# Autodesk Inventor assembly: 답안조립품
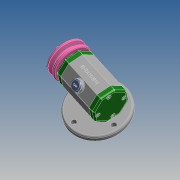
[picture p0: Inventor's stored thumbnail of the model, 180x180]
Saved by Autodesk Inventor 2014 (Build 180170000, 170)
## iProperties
Created: 2021-02
Part Number: 답안조립품
Document SubType Name: Assembly
Designer: kb542
Author: kb542
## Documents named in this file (14)
- C:\Users\kb542\Desktop\710204V1010\답안조립품.iam
- C:\Users\kb542\Desktop\710204V1010\본체.ipt
- C:\Users\kb542\Desktop\710204V1010\V벨트풀리.ipt
- C:\Users\kb542\Desktop\710204V1010\고무캡.ipt
- C:\Users\kb542\Desktop\710204V1010\너트 M8.ipt
- C:\Users\kb542\Desktop\710204V1010\뒤커버.ipt
- C:\Users\kb542\Desktop\710204V1010\베어링 15 x 32 x 9.ipt
- C:\Users\kb542\Desktop\710204V1010\볼트 M4 x 12.ipt
- C:\Users\kb542\Desktop\710204V1010\스프링와셔 8.ipt
- C:\Users\kb542\Desktop\710204V1010\앞커버.ipt
- C:\Users\kb542\Desktop\710204V1010\오일 실 15 25 7.ipt
- C:\Users\kb542\Desktop\710204V1010\와셔 8x17.ipt
- C:\Users\kb542\Desktop\710204V1010\축.ipt
- C:\Users\kb542\Desktop\710204V1010\키 3 x 3 x 12.ipt
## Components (2 placed, 2 different names)
1. V벨트풀리:1 — 각도:2
2. 고무캡:1
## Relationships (1: Angle 1)
- 각도:2 [Angle]: V벨트풀리:1
